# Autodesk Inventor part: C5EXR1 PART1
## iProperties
Created: 2006-02
Part Number: C5EXR1 PART1
Document SubType Name: Modeling
Designer: CADCIM
Density: 1 g/cm^3
Author: CADCIM
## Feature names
1. ExtrusionBlind1
2. ExtrusionThru1
3. Hole1
4. Hole2
